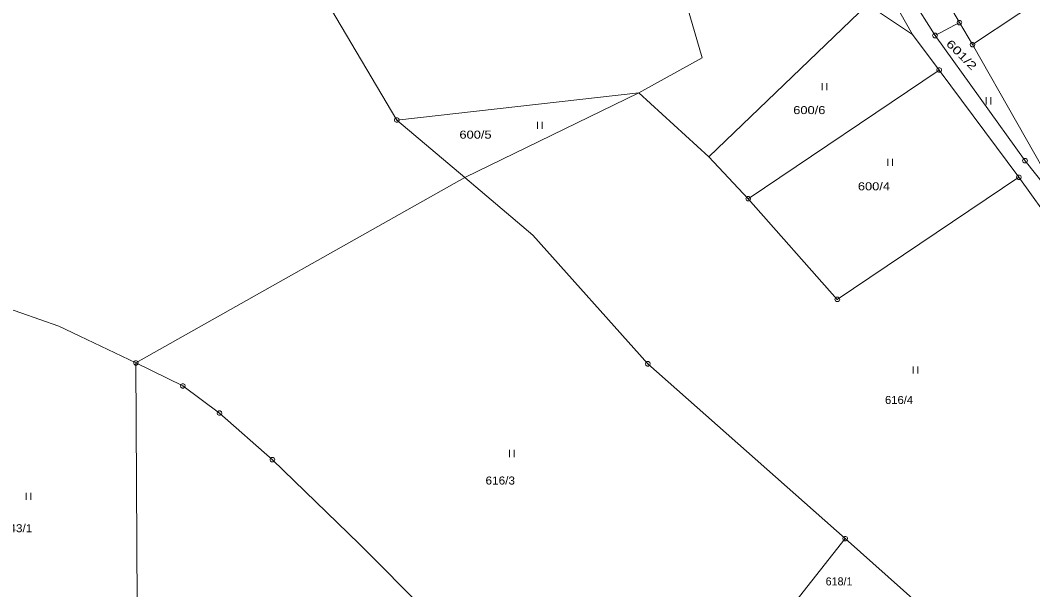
# Model space of a CAD drawing. Extents: x -687390 to -684106, y -954833 to -951648.
# Drawn here: x -687149.2 to -686934.3, y -953016.7 to -952895.8 of the extents above; entities that cross this region are included whole.
import ezdxf

# ---------------------------------------------------------------- set-up
doc = ezdxf.new("R2010")
doc.units = 0
doc.header["$LTSCALE"] = 0.68
for name, color, linetype, lineweight in [('1', 7, 'Continuous', 13), ('3', 7, 'Continuous', 13), ('8', 7, 'Continuous', 13)]:
    doc.layers.add(name, color=color, linetype=linetype, lineweight=lineweight)
doc.layers.add('2', color=7, linetype='Continuous')

msp = doc.modelspace()

# ---------------------------------------------------------------- linework, layer by layer
at = {"layer": '1'}
for p, q in [((-686970.99, -952859.32), (-686949.85, -952896.26)), ((-686955.03, -952899), (-686976.16, -952865.23)), ((-686954.13, -952906.32), (-686959.84, -952898.79)), ((-687003.06, -952924.79), (-686994.67, -952933.67)), ((-687124.67, -952968.53), (-687054.85, -952929.16)), ((-686908.24, -952969.66), (-686937.22, -952929.1)), ((-687095.7, -952989.07), (-687077.27, -953006.93)), ((-686974.1, -953005.83), (-687008.85, -953049.84)), ((-687053.63, -953030.68), (-687077.27, -953006.93))]:
    msp.add_line(p, q, dxfattribs=at)
for points in [[(-687069.27, -952916.95), (-687084.32, -952891.61), (-687068.64, -952885.43), (-687066.8, -952886.15), (-687057.45, -952877.97), (-687045.6, -952855.28), (-687030.92, -952833.92)], [(-686969.38, -952881.84), (-686959.84, -952898.79), (-686969.35, -952892.4), (-687003.06, -952924.79), (-687017.89, -952911.13), (-687004.48, -952903.7), (-687009.56, -952886.19)], [(-686930.65, -952890.02), (-686937.22, -952894.39), (-686947.05, -952900.93)], [(-686947.05, -952900.93), (-686949.85, -952896.26), (-686955.03, -952899), (-686935.91, -952925.58), (-686924.11, -952940.37), (-686907.26, -952963.03)], [(-686947.05, -952900.93), (-686928.21, -952934), (-686924.11, -952940.37)], [(-687069.27, -952916.95), (-687017.89, -952911.13), (-687054.85, -952929.16)], [(-687040.42, -952941.36), (-687054.85, -952929.16), (-687069.27, -952916.95)], [(-686940.23, -953036.04), (-686974.1, -953005.83), (-687015.99, -952968.71), (-687040.42, -952941.36)], [(-687124.67, -952968.53), (-687141.06, -952960.72), (-687153.12, -952956.45)], [(-687095.7, -952989.07), (-687106.92, -952979.17), (-687114.72, -952973.41), (-687124.67, -952968.53), (-687124.1, -953070.77)]]:
    msp.add_lwpolyline(points, dxfattribs=at)
msp.add_lwpolyline([(-686954.13, -952906.32), (-686937.22, -952929.1), (-686975.77, -952955.02), (-686994.67, -952933.67)], close=True, dxfattribs=at)
at = {"layer": '3'}
for p, q in [((-686978.98, -952909.13), (-686978.98, -952910.63)), ((-686977.98, -952910.63), (-686977.98, -952909.13)), ((-686944.16, -952912.12), (-686944.16, -952913.62)), ((-686943.16, -952913.62), (-686943.16, -952912.12)), ((-687039.44, -952917.29), (-687039.44, -952918.79)), ((-687038.44, -952918.79), (-687038.44, -952917.29)), ((-686965.04, -952925.18), (-686965.04, -952926.68)), ((-686964.04, -952926.68), (-686964.04, -952925.18)), ((-686959.69, -952969.25), (-686959.69, -952970.75)), ((-686958.69, -952970.75), (-686958.69, -952969.25)), ((-687045.35, -952987), (-687045.35, -952988.5)), ((-687044.35, -952988.5), (-687044.35, -952987)), ((-687147.96, -952996.1), (-687147.96, -952997.6)), ((-687146.96, -952997.6), (-687146.96, -952996.1))]:
    msp.add_line(p, q, dxfattribs=at)
at = {"layer": '8'}
for p, q in [((-686949.97, -952896.26), (-686949.73, -952896.26)), ((-686955.15, -952899), (-686954.91, -952899)), ((-686947.17, -952900.93), (-686946.93, -952900.93)), ((-686954.25, -952906.32), (-686954.01, -952906.32)), ((-687069.39, -952916.95), (-687069.15, -952916.95)), ((-686936.03, -952925.58), (-686935.79, -952925.58)), ((-686937.34, -952929.1), (-686937.1, -952929.1)), ((-686994.79, -952933.67), (-686994.55, -952933.67)), ((-686975.89, -952955.02), (-686975.65, -952955.02)), ((-687124.79, -952968.53), (-687124.55, -952968.53)), ((-687016.11, -952968.71), (-687015.87, -952968.71)), ((-687114.84, -952973.41), (-687114.6, -952973.41)), ((-687107.04, -952979.17), (-687106.8, -952979.17)), ((-687095.82, -952989.07), (-687095.58, -952989.07)), ((-686974.22, -953005.83), (-686973.98, -953005.83))]:
    msp.add_line(p, q, dxfattribs=at)
for points in [[(-686949.7, -952895.78), (-686949.45, -952895.96), (-686949.35, -952896.25), (-686949.45, -952896.54), (-686949.7, -952896.72), (-686950.01, -952896.72), (-686950.26, -952896.54), (-686950.36, -952896.25), (-686950.26, -952895.96), (-686950.01, -952895.78)], [(-686954.88, -952898.52), (-686954.63, -952898.7), (-686954.53, -952898.99), (-686954.63, -952899.28), (-686954.88, -952899.46), (-686955.19, -952899.46), (-686955.44, -952899.28), (-686955.54, -952898.99), (-686955.44, -952898.7), (-686955.19, -952898.52)], [(-686946.9, -952900.45), (-686946.65, -952900.63), (-686946.55, -952900.92), (-686946.65, -952901.21), (-686946.9, -952901.39), (-686947.21, -952901.39), (-686947.46, -952901.21), (-686947.56, -952900.92), (-686947.46, -952900.63), (-686947.21, -952900.45)], [(-686953.98, -952905.84), (-686953.73, -952906.02), (-686953.63, -952906.31), (-686953.73, -952906.6), (-686953.98, -952906.78), (-686954.29, -952906.78), (-686954.54, -952906.6), (-686954.64, -952906.31), (-686954.54, -952906.02), (-686954.29, -952905.84)], [(-687069.12, -952916.47), (-687068.87, -952916.65), (-687068.77, -952916.94), (-687068.87, -952917.23), (-687069.12, -952917.41), (-687069.43, -952917.41), (-687069.68, -952917.23), (-687069.78, -952916.94), (-687069.68, -952916.65), (-687069.43, -952916.47)], [(-686935.76, -952925.1), (-686935.51, -952925.28), (-686935.41, -952925.57), (-686935.51, -952925.86), (-686935.76, -952926.04), (-686936.07, -952926.04), (-686936.32, -952925.86), (-686936.42, -952925.57), (-686936.32, -952925.28), (-686936.07, -952925.1)], [(-686937.07, -952928.62), (-686936.82, -952928.8), (-686936.72, -952929.09), (-686936.82, -952929.38), (-686937.07, -952929.56), (-686937.38, -952929.56), (-686937.63, -952929.38), (-686937.73, -952929.09), (-686937.63, -952928.8), (-686937.38, -952928.62)], [(-686994.52, -952933.19), (-686994.27, -952933.37), (-686994.17, -952933.66), (-686994.27, -952933.95), (-686994.52, -952934.13), (-686994.83, -952934.13), (-686995.08, -952933.95), (-686995.18, -952933.66), (-686995.08, -952933.37), (-686994.83, -952933.19)], [(-686975.62, -952954.54), (-686975.37, -952954.72), (-686975.27, -952955.01), (-686975.37, -952955.3), (-686975.62, -952955.48), (-686975.93, -952955.48), (-686976.18, -952955.3), (-686976.28, -952955.01), (-686976.18, -952954.72), (-686975.93, -952954.54)], [(-687124.52, -952968.05), (-687124.27, -952968.23), (-687124.17, -952968.52), (-687124.27, -952968.81), (-687124.52, -952968.99), (-687124.83, -952968.99), (-687125.08, -952968.81), (-687125.18, -952968.52), (-687125.08, -952968.23), (-687124.83, -952968.05)], [(-687015.84, -952968.23), (-687015.59, -952968.41), (-687015.49, -952968.7), (-687015.59, -952968.99), (-687015.84, -952969.17), (-687016.15, -952969.17), (-687016.4, -952968.99), (-687016.5, -952968.7), (-687016.4, -952968.41), (-687016.15, -952968.23)], [(-687114.57, -952972.93), (-687114.32, -952973.11), (-687114.22, -952973.4), (-687114.32, -952973.69), (-687114.57, -952973.87), (-687114.88, -952973.87), (-687115.13, -952973.69), (-687115.23, -952973.4), (-687115.13, -952973.11), (-687114.88, -952972.93)], [(-687106.77, -952978.69), (-687106.52, -952978.87), (-687106.42, -952979.16), (-687106.52, -952979.45), (-687106.77, -952979.63), (-687107.08, -952979.63), (-687107.33, -952979.45), (-687107.43, -952979.16), (-687107.33, -952978.87), (-687107.08, -952978.69)], [(-687095.55, -952988.59), (-687095.3, -952988.77), (-687095.2, -952989.06), (-687095.3, -952989.35), (-687095.55, -952989.53), (-687095.86, -952989.53), (-687096.11, -952989.35), (-687096.21, -952989.06), (-687096.11, -952988.77), (-687095.86, -952988.59)], [(-686973.95, -953005.35), (-686973.7, -953005.53), (-686973.6, -953005.82), (-686973.7, -953006.11), (-686973.95, -953006.29), (-686974.26, -953006.29), (-686974.51, -953006.11), (-686974.61, -953005.82), (-686974.51, -953005.53), (-686974.26, -953005.35)]]:
    msp.add_lwpolyline(points, close=True, dxfattribs=at)

# ---------------------------------------------------------------- texts
at = {"layer": '2', "width": 1.4}
msp.add_text('601/2', height=1.7, rotation=315.012, dxfattribs=at).set_placement((-686952.815, -952900.885))
at = {"layer": '2'}
for s, width, p in [('600/6', 1.2, (-686985.126, -952915.68)), ('600/5', 1.2, (-687055.996, -952920.89)), ('600/4', 1.2, (-686971.406, -952931.86)), ('616/4', 1.05, (-686965.646, -952977.23)), ('616/3', 1.1, (-687050.456, -952994.34)), ('643/1', 1.1, (-687152.936, -953004.47))]:
    msp.add_text(s, height=1.7, dxfattribs=dict(at, width=width)).set_placement(p)
msp.add_text('618/1', height=1.7, dxfattribs=at).set_placement((-686978.246, -953015.76))

doc.saveas('drawing.dxf')
